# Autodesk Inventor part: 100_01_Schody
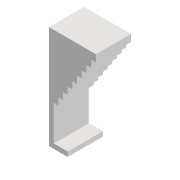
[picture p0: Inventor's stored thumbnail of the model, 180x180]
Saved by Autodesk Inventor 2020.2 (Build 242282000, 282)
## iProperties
Created: 2020-03
Part Number: 100_01_Schody
Material: Beton wzmocniony włóknem szklanym
Document SubType Name: Modeling
Designer: F.Stasiak
Density: 1.7 g/cm^3
Appearance: Płaskie — polerowane szare
Catalog Web Link: www.expertbooks.pl
Manager: www.cadconsulting.pl
Company: Fabian Stasiak CAD Consulting
Author: F.Stasiak
Subject: Zbiór ćwiczeń. Autodesk Inventor 2020. Kurs Professional
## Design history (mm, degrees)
sketch "Szkic1"
  geometry: L1 (0, 0)-(2000, 0); L2 (2000, 0)-(2000, -300); L3 (2000, -300)-(1800, -300); L4 (1800, -300)-(1800, -600); L5 (1800, -600)-(1600, -600); L6 (1600, -600)-(1600, -900); L7 (1600, -900)-(1400, -900); L8 (1400, -900)-(1400, -1200); L9 (1400, -1200)-(1200, -1200); L10 (1200, -1200)-(1200, -1500); L11 (1200, -1500)-(1000, -1500); L12 (1000, -1500)-(1000, -1800); L13 (1000, -1800)-(800, -1800); L14 (800, -1800)-(800, -2100); L15 (800, -2100)-(600, -2100); L16 (600, -2100)-(600, -2400); L17 (600, -2400)-(400, -2400); L18 (400, -2400)-(400, -2700); L19 (400, -2700)-(200, -2700); L20 (200, -2700)-(200, -4200); L21 (200, -4200)-(800, -4200); L22 (800, -4200)-(800, -4400); L23 (800, -4400)-(0, -4400); L24 (0, -4400)-(0, 0)
  constraints: 48 end point, 21 perpendicular, 16 parallel, 2 vertical, 1 horizontal
  dimensions: "d0" = 2000 distance of L1.start L1.end; "d1" = 300 distance of L1.end L2.end; "d2" = 200 distance of L2.end L3.end; "d3" = 1500 distance of L19.end L20.end; "d4" = 600 distance of L20.end L21.end; "d5" = 200 distance of L21.end L22.end
extrude "Wyciągnięcie proste1" new body sketch "Szkic1" stored distance "d6" = 1500; taper "d7" = 0 deg
node "Bryła1"
